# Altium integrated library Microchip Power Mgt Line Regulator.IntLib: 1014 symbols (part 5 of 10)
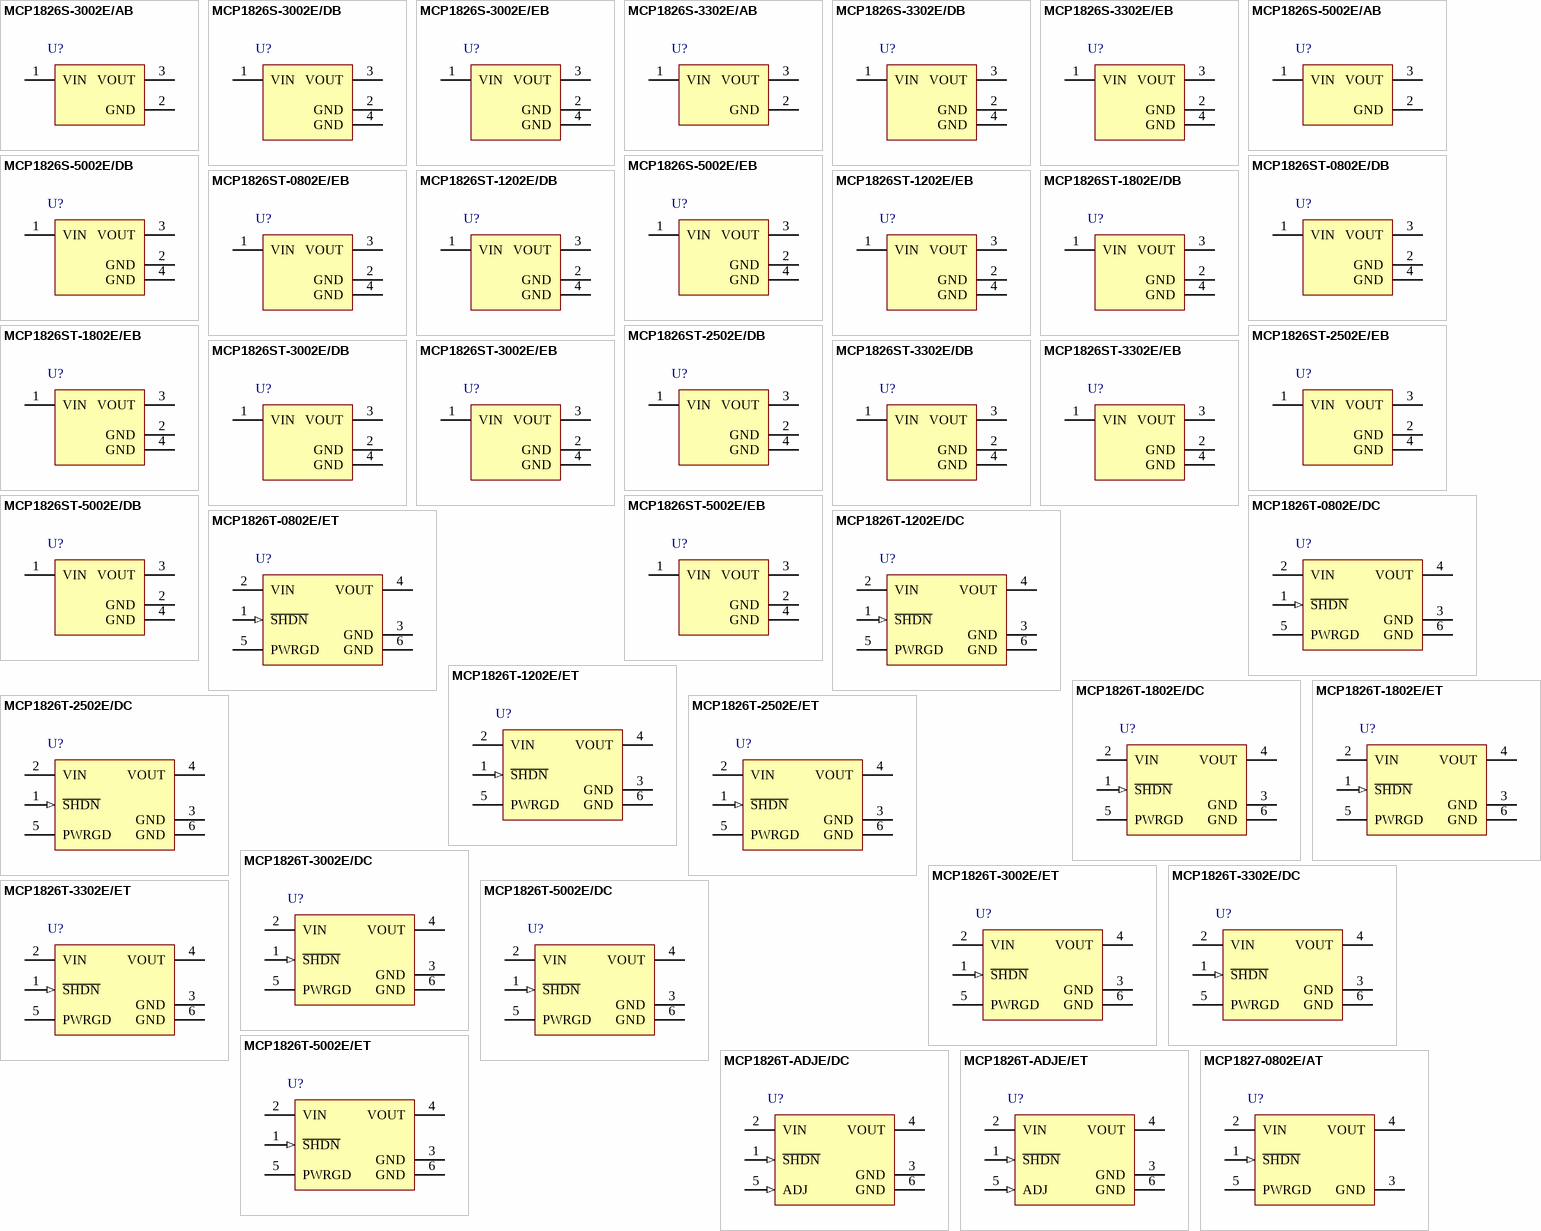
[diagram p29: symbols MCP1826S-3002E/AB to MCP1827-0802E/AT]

## MCP1826T-2502E/DC
designator U?
1000 mA, Low Voltage, Low Quiescent Current LDO Regulator, 5-Pin SOT-223, Extended Temperature, Tape and Reel
footprint SOT-223-DC5_N (SOT223, 6-Leads, Body 6.5x3.5mm, Pitch 1.27mm, Lead Span 7mm, IPC Medium Density)
footprint SOT-223-DC5_L (SOT223, 6-Leads, Body 6.5x3.5mm, Pitch 1.27mm, Lead Span 7mm, IPC High Density)
footprint SOT-223-DC5_M (SOT223, 6-Leads, Body 6.5x3.5mm, Pitch 1.27mm, Lead Span 7mm, IPC Low Density)
pins: 1 ~{SHDN} (in), 2 VIN (power), 3 GND (power), 4 VOUT (power), 5 PWRGD (power), 6 GND (power)

## MCP1826T-2502E/ET
designator U?
1000 mA, Low Voltage, Low Quiescent Current LDO Regulator, 5-Pin DDPAK, Extended Temperature, Tape and Reel
footprint DDPAK-ET5_N (D2-PAK, 6-Leads, Body 9x10.2mm, Pitch 1.7mm, Lead Span 14.9mm, IPC Medium Density)
footprint DDPAK-ET5_L (D2-PAK, 6-Leads, Body 9x10.2mm, Pitch 1.7mm, Lead Span 14.9mm, IPC High Density)
footprint DDPAK-ET5_M (D2-PAK, 6-Leads, Body 9x10.2mm, Pitch 1.7mm, Lead Span 14.9mm, IPC Low Density)
pins: 1 ~{SHDN} (in), 2 VIN (power), 3 GND (power), 4 VOUT (power), 5 PWRGD (power), 6 GND (power)

## MCP1826T-3002E/DC
designator U?
1000 mA, Low Voltage, Low Quiescent Current LDO Regulator, 5-Pin SOT-223, Extended Temperature, Tape and Reel
footprint SOT-223-DC5_N (SOT223, 6-Leads, Body 6.5x3.5mm, Pitch 1.27mm, Lead Span 7mm, IPC Medium Density)
footprint SOT-223-DC5_L (SOT223, 6-Leads, Body 6.5x3.5mm, Pitch 1.27mm, Lead Span 7mm, IPC High Density)
footprint SOT-223-DC5_M (SOT223, 6-Leads, Body 6.5x3.5mm, Pitch 1.27mm, Lead Span 7mm, IPC Low Density)
pins: 1 ~{SHDN} (in), 2 VIN (power), 3 GND (power), 4 VOUT (power), 5 PWRGD (power), 6 GND (power)

## MCP1826T-3002E/ET
designator U?
1000 mA, Low Voltage, Low Quiescent Current LDO Regulator, 5-Pin DDPAK, Extended Temperature, Tape and Reel
footprint DDPAK-ET5_N (D2-PAK, 6-Leads, Body 9x10.2mm, Pitch 1.7mm, Lead Span 14.9mm, IPC Medium Density)
footprint DDPAK-ET5_L (D2-PAK, 6-Leads, Body 9x10.2mm, Pitch 1.7mm, Lead Span 14.9mm, IPC High Density)
footprint DDPAK-ET5_M (D2-PAK, 6-Leads, Body 9x10.2mm, Pitch 1.7mm, Lead Span 14.9mm, IPC Low Density)
pins: 1 ~{SHDN} (in), 2 VIN (power), 3 GND (power), 4 VOUT (power), 5 PWRGD (power), 6 GND (power)

## MCP1826T-3302E/DC
designator U?
1000 mA, Low Voltage, Low Quiescent Current LDO Regulator, 5-Pin SOT-223, Extended Temperature, Tape and Reel
footprint SOT-223-DC5_N (SOT223, 6-Leads, Body 6.5x3.5mm, Pitch 1.27mm, Lead Span 7mm, IPC Medium Density)
footprint SOT-223-DC5_L (SOT223, 6-Leads, Body 6.5x3.5mm, Pitch 1.27mm, Lead Span 7mm, IPC High Density)
footprint SOT-223-DC5_M (SOT223, 6-Leads, Body 6.5x3.5mm, Pitch 1.27mm, Lead Span 7mm, IPC Low Density)
pins: 1 ~{SHDN} (in), 2 VIN (power), 3 GND (power), 4 VOUT (power), 5 PWRGD (power), 6 GND (power)

## MCP1826T-3302E/ET
designator U?
1000 mA, Low Voltage, Low Quiescent Current LDO Regulator, 5-Pin DDPAK, Extended Temperature, Tape and Reel
footprint DDPAK-ET5_N (D2-PAK, 6-Leads, Body 9x10.2mm, Pitch 1.7mm, Lead Span 14.9mm, IPC Medium Density)
footprint DDPAK-ET5_L (D2-PAK, 6-Leads, Body 9x10.2mm, Pitch 1.7mm, Lead Span 14.9mm, IPC High Density)
footprint DDPAK-ET5_M (D2-PAK, 6-Leads, Body 9x10.2mm, Pitch 1.7mm, Lead Span 14.9mm, IPC Low Density)
pins: 1 ~{SHDN} (in), 2 VIN (power), 3 GND (power), 4 VOUT (power), 5 PWRGD (power), 6 GND (power)

## MCP1826T-5002E/DC
designator U?
1000 mA, Low Voltage, Low Quiescent Current LDO Regulator, 5-Pin SOT-223, Extended Temperature, Tape and Reel
footprint SOT-223-DC5_N (SOT223, 6-Leads, Body 6.5x3.5mm, Pitch 1.27mm, Lead Span 7mm, IPC Medium Density)
footprint SOT-223-DC5_L (SOT223, 6-Leads, Body 6.5x3.5mm, Pitch 1.27mm, Lead Span 7mm, IPC High Density)
footprint SOT-223-DC5_M (SOT223, 6-Leads, Body 6.5x3.5mm, Pitch 1.27mm, Lead Span 7mm, IPC Low Density)
pins: 1 ~{SHDN} (in), 2 VIN (power), 3 GND (power), 4 VOUT (power), 5 PWRGD (power), 6 GND (power)

## MCP1826T-5002E/ET
designator U?
1000 mA, Low Voltage, Low Quiescent Current LDO Regulator, 5-Pin DDPAK, Extended Temperature, Tape and Reel
footprint DDPAK-ET5_N (D2-PAK, 6-Leads, Body 9x10.2mm, Pitch 1.7mm, Lead Span 14.9mm, IPC Medium Density)
footprint DDPAK-ET5_L (D2-PAK, 6-Leads, Body 9x10.2mm, Pitch 1.7mm, Lead Span 14.9mm, IPC High Density)
footprint DDPAK-ET5_M (D2-PAK, 6-Leads, Body 9x10.2mm, Pitch 1.7mm, Lead Span 14.9mm, IPC Low Density)
pins: 1 ~{SHDN} (in), 2 VIN (power), 3 GND (power), 4 VOUT (power), 5 PWRGD (power), 6 GND (power)

## MCP1826T-ADJE/DC
designator U?
1000 mA, Low Voltage, Low Quiescent Current LDO Regulator, 5-Pin SOT-223, Extended Temperature, Tape and Reel
footprint SOT-223-DC5_N (SOT223, 6-Leads, Body 6.5x3.5mm, Pitch 1.27mm, Lead Span 7mm, IPC Medium Density)
footprint SOT-223-DC5_L (SOT223, 6-Leads, Body 6.5x3.5mm, Pitch 1.27mm, Lead Span 7mm, IPC High Density)
footprint SOT-223-DC5_M (SOT223, 6-Leads, Body 6.5x3.5mm, Pitch 1.27mm, Lead Span 7mm, IPC Low Density)
pins: 1 ~{SHDN} (in), 2 VIN (power), 3 GND (power), 4 VOUT (power), 5 ADJ (in), 6 GND (power)

## MCP1826T-ADJE/ET
designator U?
1000 mA, Low Voltage, Low Quiescent Current LDO Regulator, 5-Pin DDPAK, Extended Temperature, Tape and Reel
footprint DDPAK-ET5_N (D2-PAK, 6-Leads, Body 9x10.2mm, Pitch 1.7mm, Lead Span 14.9mm, IPC Medium Density)
footprint DDPAK-ET5_L (D2-PAK, 6-Leads, Body 9x10.2mm, Pitch 1.7mm, Lead Span 14.9mm, IPC High Density)
footprint DDPAK-ET5_M (D2-PAK, 6-Leads, Body 9x10.2mm, Pitch 1.7mm, Lead Span 14.9mm, IPC Low Density)
pins: 1 ~{SHDN} (in), 2 VIN (power), 3 GND (power), 4 VOUT (power), 5 ADJ (in), 6 GND (power)

## MCP1827-0802E/AT
designator U?
1.5A, Low Voltage, Low Quiescent Current LDO Regulator, 5-Pin TO-220, Extended Temperature
footprint TO-220-AT5 (TO, Thru-Hole, Vertical, Heatsink Mounted; 5 In-Line Leads; Pitch 1.70 mm)
pins: 1 ~{SHDN} (in), 2 VIN (power), 3 GND (power), 4 VOUT (power), 5 PWRGD (power)

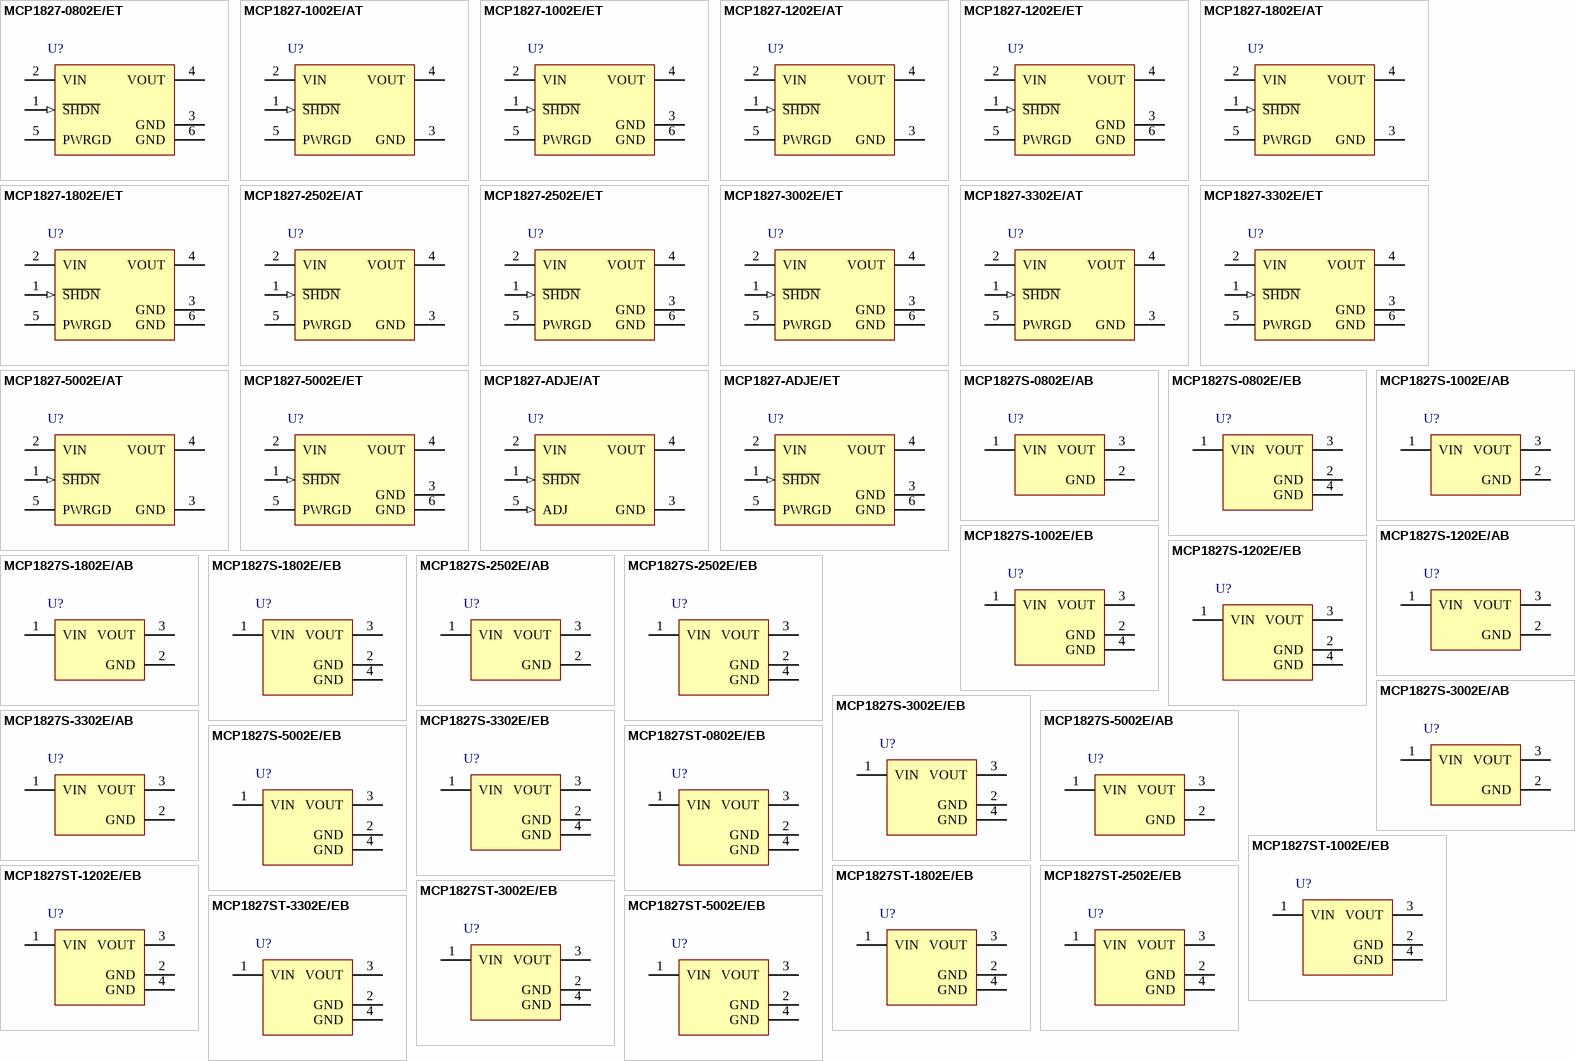
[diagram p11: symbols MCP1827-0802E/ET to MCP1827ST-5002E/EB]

## MCP1827-0802E/ET
designator U?
1.5A, Low Voltage, Low Quiescent Current LDO Regulator, 5-Pin DDPAK, Extended Temperature
footprint DDPAK-ET5_N (D2-PAK, 6-Leads, Body 9x10.2mm, Pitch 1.7mm, Lead Span 14.9mm, IPC Medium Density)
footprint DDPAK-ET5_L (D2-PAK, 6-Leads, Body 9x10.2mm, Pitch 1.7mm, Lead Span 14.9mm, IPC High Density)
footprint DDPAK-ET5_M (D2-PAK, 6-Leads, Body 9x10.2mm, Pitch 1.7mm, Lead Span 14.9mm, IPC Low Density)
pins: 1 ~{SHDN} (in), 2 VIN (power), 3 GND (power), 4 VOUT (power), 5 PWRGD (power), 6 GND (power)

## MCP1827-1002E/AT
designator U?
1.5A, Low Voltage, Low Quiescent Current LDO Regulator, 5-Pin TO-220, Extended Temperature
footprint TO-220-AT5 (TO, Thru-Hole, Vertical, Heatsink Mounted; 5 In-Line Leads; Pitch 1.70 mm)
pins: 1 ~{SHDN} (in), 2 VIN (power), 3 GND (power), 4 VOUT (power), 5 PWRGD (power)

## MCP1827-1002E/ET
designator U?
1.5A, Low Voltage, Low Quiescent Current LDO Regulator, 5-Pin DDPAK, Extended Temperature
footprint DDPAK-ET5_N (D2-PAK, 6-Leads, Body 9x10.2mm, Pitch 1.7mm, Lead Span 14.9mm, IPC Medium Density)
footprint DDPAK-ET5_L (D2-PAK, 6-Leads, Body 9x10.2mm, Pitch 1.7mm, Lead Span 14.9mm, IPC High Density)
footprint DDPAK-ET5_M (D2-PAK, 6-Leads, Body 9x10.2mm, Pitch 1.7mm, Lead Span 14.9mm, IPC Low Density)
pins: 1 ~{SHDN} (in), 2 VIN (power), 3 GND (power), 4 VOUT (power), 5 PWRGD (power), 6 GND (power)

## MCP1827-1202E/AT
designator U?
1.5A, Low Voltage, Low Quiescent Current LDO Regulator, 5-Pin TO-220, Extended Temperature
footprint TO-220-AT5 (TO, Thru-Hole, Vertical, Heatsink Mounted; 5 In-Line Leads; Pitch 1.70 mm)
pins: 1 ~{SHDN} (in), 2 VIN (power), 3 GND (power), 4 VOUT (power), 5 PWRGD (power)

## MCP1827-1202E/ET
designator U?
1.5A, Low Voltage, Low Quiescent Current LDO Regulator, 5-Pin DDPAK, Extended Temperature
footprint DDPAK-ET5_N (D2-PAK, 6-Leads, Body 9x10.2mm, Pitch 1.7mm, Lead Span 14.9mm, IPC Medium Density)
footprint DDPAK-ET5_L (D2-PAK, 6-Leads, Body 9x10.2mm, Pitch 1.7mm, Lead Span 14.9mm, IPC High Density)
footprint DDPAK-ET5_M (D2-PAK, 6-Leads, Body 9x10.2mm, Pitch 1.7mm, Lead Span 14.9mm, IPC Low Density)
pins: 1 ~{SHDN} (in), 2 VIN (power), 3 GND (power), 4 VOUT (power), 5 PWRGD (power), 6 GND (power)

## MCP1827-1802E/AT
designator U?
1.5A, Low Voltage, Low Quiescent Current LDO Regulator, 5-Pin TO-220, Extended Temperature
footprint TO-220-AT5 (TO, Thru-Hole, Vertical, Heatsink Mounted; 5 In-Line Leads; Pitch 1.70 mm)
pins: 1 ~{SHDN} (in), 2 VIN (power), 3 GND (power), 4 VOUT (power), 5 PWRGD (power)

## MCP1827-1802E/ET
designator U?
1.5A, Low Voltage, Low Quiescent Current LDO Regulator, 5-Pin DDPAK, Extended Temperature
footprint DDPAK-ET5_N (D2-PAK, 6-Leads, Body 9x10.2mm, Pitch 1.7mm, Lead Span 14.9mm, IPC Medium Density)
footprint DDPAK-ET5_L (D2-PAK, 6-Leads, Body 9x10.2mm, Pitch 1.7mm, Lead Span 14.9mm, IPC High Density)
footprint DDPAK-ET5_M (D2-PAK, 6-Leads, Body 9x10.2mm, Pitch 1.7mm, Lead Span 14.9mm, IPC Low Density)
pins: 1 ~{SHDN} (in), 2 VIN (power), 3 GND (power), 4 VOUT (power), 5 PWRGD (power), 6 GND (power)

## MCP1827-2502E/AT
designator U?
1.5A, Low Voltage, Low Quiescent Current LDO Regulator, 5-Pin TO-220, Extended Temperature
footprint TO-220-AT5 (TO, Thru-Hole, Vertical, Heatsink Mounted; 5 In-Line Leads; Pitch 1.70 mm)
pins: 1 ~{SHDN} (in), 2 VIN (power), 3 GND (power), 4 VOUT (power), 5 PWRGD (power)

## MCP1827-2502E/ET
designator U?
1.5A, Low Voltage, Low Quiescent Current LDO Regulator, 5-Pin DDPAK, Extended Temperature
footprint DDPAK-ET5_N (D2-PAK, 6-Leads, Body 9x10.2mm, Pitch 1.7mm, Lead Span 14.9mm, IPC Medium Density)
footprint DDPAK-ET5_L (D2-PAK, 6-Leads, Body 9x10.2mm, Pitch 1.7mm, Lead Span 14.9mm, IPC High Density)
footprint DDPAK-ET5_M (D2-PAK, 6-Leads, Body 9x10.2mm, Pitch 1.7mm, Lead Span 14.9mm, IPC Low Density)
pins: 1 ~{SHDN} (in), 2 VIN (power), 3 GND (power), 4 VOUT (power), 5 PWRGD (power), 6 GND (power)

## MCP1827-3002E/ET
designator U?
1.5A, Low Voltage, Low Quiescent Current LDO Regulator, 5-Pin DDPAK, Extended Temperature
footprint DDPAK-ET5_N (D2-PAK, 6-Leads, Body 9x10.2mm, Pitch 1.7mm, Lead Span 14.9mm, IPC Medium Density)
footprint DDPAK-ET5_L (D2-PAK, 6-Leads, Body 9x10.2mm, Pitch 1.7mm, Lead Span 14.9mm, IPC High Density)
footprint DDPAK-ET5_M (D2-PAK, 6-Leads, Body 9x10.2mm, Pitch 1.7mm, Lead Span 14.9mm, IPC Low Density)
pins: 1 ~{SHDN} (in), 2 VIN (power), 3 GND (power), 4 VOUT (power), 5 PWRGD (power), 6 GND (power)

## MCP1827-3302E/AT
designator U?
1.5A, Low Voltage, Low Quiescent Current LDO Regulator, 5-Pin TO-220, Extended Temperature
footprint TO-220-AT5 (TO, Thru-Hole, Vertical, Heatsink Mounted; 5 In-Line Leads; Pitch 1.70 mm)
pins: 1 ~{SHDN} (in), 2 VIN (power), 3 GND (power), 4 VOUT (power), 5 PWRGD (power)

## MCP1827-3302E/ET
designator U?
1.5A, Low Voltage, Low Quiescent Current LDO Regulator, 5-Pin DDPAK, Extended Temperature
footprint DDPAK-ET5_N (D2-PAK, 6-Leads, Body 9x10.2mm, Pitch 1.7mm, Lead Span 14.9mm, IPC Medium Density)
footprint DDPAK-ET5_L (D2-PAK, 6-Leads, Body 9x10.2mm, Pitch 1.7mm, Lead Span 14.9mm, IPC High Density)
footprint DDPAK-ET5_M (D2-PAK, 6-Leads, Body 9x10.2mm, Pitch 1.7mm, Lead Span 14.9mm, IPC Low Density)
pins: 1 ~{SHDN} (in), 2 VIN (power), 3 GND (power), 4 VOUT (power), 5 PWRGD (power), 6 GND (power)

## MCP1827-5002E/AT
designator U?
1.5A, Low Voltage, Low Quiescent Current LDO Regulator, 5-Pin TO-220, Extended Temperature
footprint TO-220-AT5 (TO, Thru-Hole, Vertical, Heatsink Mounted; 5 In-Line Leads; Pitch 1.70 mm)
pins: 1 ~{SHDN} (in), 2 VIN (power), 3 GND (power), 4 VOUT (power), 5 PWRGD (power)

## MCP1827-5002E/ET
designator U?
1.5A, Low Voltage, Low Quiescent Current LDO Regulator, 5-Pin DDPAK, Extended Temperature
footprint DDPAK-ET5_N (D2-PAK, 6-Leads, Body 9x10.2mm, Pitch 1.7mm, Lead Span 14.9mm, IPC Medium Density)
footprint DDPAK-ET5_L (D2-PAK, 6-Leads, Body 9x10.2mm, Pitch 1.7mm, Lead Span 14.9mm, IPC High Density)
footprint DDPAK-ET5_M (D2-PAK, 6-Leads, Body 9x10.2mm, Pitch 1.7mm, Lead Span 14.9mm, IPC Low Density)
pins: 1 ~{SHDN} (in), 2 VIN (power), 3 GND (power), 4 VOUT (power), 5 PWRGD (power), 6 GND (power)

## MCP1827-ADJE/AT
designator U?
1.5A, Low Voltage, Low Quiescent Current LDO Regulator, 5-Pin TO-220, Extended Temperature
footprint TO-220-AT5 (TO, Thru-Hole, Vertical, Heatsink Mounted; 5 In-Line Leads; Pitch 1.70 mm)
pins: 1 ~{SHDN} (in), 2 VIN (power), 3 GND (power), 4 VOUT (power), 5 ADJ (in)

## MCP1827-ADJE/ET
designator U?
1.5A, Low Voltage, Low Quiescent Current LDO Regulator, 5-Pin DDPAK, Extended Temperature
footprint DDPAK-ET5_N (D2-PAK, 6-Leads, Body 9x10.2mm, Pitch 1.7mm, Lead Span 14.9mm, IPC Medium Density)
footprint DDPAK-ET5_L (D2-PAK, 6-Leads, Body 9x10.2mm, Pitch 1.7mm, Lead Span 14.9mm, IPC High Density)
footprint DDPAK-ET5_M (D2-PAK, 6-Leads, Body 9x10.2mm, Pitch 1.7mm, Lead Span 14.9mm, IPC Low Density)
pins: 1 ~{SHDN} (in), 2 VIN (power), 3 GND (power), 4 VOUT (power), 5 PWRGD (power), 6 GND (power)

## MCP1827S-0802E/AB
designator U?
1.5A, Low Voltage, Low Quiescent Current LDO Regulator, 3-Pin TO-220, Extended Temperature
footprint TO-220-AB3 (TO, Thru-Hole, Vertical, Heatsink Mounted; 3 In-Line Leads; Pitch 2.54 mm)
pins: 1 VIN (power), 2 GND (power), 3 VOUT (power)

## MCP1827S-0802E/EB
designator U?
1.5A, Low Voltage, Low Quiescent Current LDO Regulator, 3-Pin DDPAK, Extended Temperature
footprint DDPAK-EB3_N (D2-PAK, 4-Leads, Body 9x10.2mm, Pitch 2.54mm, Lead Span 14.9mm, IPC Medium Density)
footprint DDPAK-EB3_L (D2-PAK, 4-Leads, Body 9x10.2mm, Pitch 2.54mm, Lead Span 14.9mm, IPC High Density)
footprint DDPAK-EB3_M (D2-PAK, 4-Leads, Body 9x10.2mm, Pitch 2.54mm, Lead Span 14.9mm, IPC Low Density)
pins: 1 VIN (power), 2 GND (power), 3 VOUT (power), 4 GND (power)

## MCP1827S-1002E/AB
designator U?
1.5A, Low Voltage, Low Quiescent Current LDO Regulator, 3-Pin TO-220, Extended Temperature
footprint TO-220-AB3 (TO, Thru-Hole, Vertical, Heatsink Mounted; 3 In-Line Leads; Pitch 2.54 mm)
pins: 1 VIN (power), 2 GND (power), 3 VOUT (power)

## MCP1827S-1002E/EB
designator U?
1.5A, Low Voltage, Low Quiescent Current LDO Regulator, 3-Pin DDPAK, Extended Temperature
footprint DDPAK-EB3_N (D2-PAK, 4-Leads, Body 9x10.2mm, Pitch 2.54mm, Lead Span 14.9mm, IPC Medium Density)
footprint DDPAK-EB3_L (D2-PAK, 4-Leads, Body 9x10.2mm, Pitch 2.54mm, Lead Span 14.9mm, IPC High Density)
footprint DDPAK-EB3_M (D2-PAK, 4-Leads, Body 9x10.2mm, Pitch 2.54mm, Lead Span 14.9mm, IPC Low Density)
pins: 1 VIN (power), 2 GND (power), 3 VOUT (power), 4 GND (power)

## MCP1827S-1202E/AB
designator U?
1.5A, Low Voltage, Low Quiescent Current LDO Regulator, 3-Pin TO-220, Extended Temperature
footprint TO-220-AB3 (TO, Thru-Hole, Vertical, Heatsink Mounted; 3 In-Line Leads; Pitch 2.54 mm)
pins: 1 VIN (power), 2 GND (power), 3 VOUT (power)

## MCP1827S-1202E/EB
designator U?
1.5A, Low Voltage, Low Quiescent Current LDO Regulator, 3-Pin DDPAK, Extended Temperature
footprint DDPAK-EB3_N (D2-PAK, 4-Leads, Body 9x10.2mm, Pitch 2.54mm, Lead Span 14.9mm, IPC Medium Density)
footprint DDPAK-EB3_L (D2-PAK, 4-Leads, Body 9x10.2mm, Pitch 2.54mm, Lead Span 14.9mm, IPC High Density)
footprint DDPAK-EB3_M (D2-PAK, 4-Leads, Body 9x10.2mm, Pitch 2.54mm, Lead Span 14.9mm, IPC Low Density)
pins: 1 VIN (power), 2 GND (power), 3 VOUT (power), 4 GND (power)

## MCP1827S-1802E/AB
designator U?
1.5A, Low Voltage, Low Quiescent Current LDO Regulator, 3-Pin TO-220, Extended Temperature
footprint TO-220-AB3 (TO, Thru-Hole, Vertical, Heatsink Mounted; 3 In-Line Leads; Pitch 2.54 mm)
pins: 1 VIN (power), 2 GND (power), 3 VOUT (power)

## MCP1827S-1802E/EB
designator U?
1.5A, Low Voltage, Low Quiescent Current LDO Regulator, 3-Pin DDPAK, Extended Temperature
footprint DDPAK-EB3_N (D2-PAK, 4-Leads, Body 9x10.2mm, Pitch 2.54mm, Lead Span 14.9mm, IPC Medium Density)
footprint DDPAK-EB3_L (D2-PAK, 4-Leads, Body 9x10.2mm, Pitch 2.54mm, Lead Span 14.9mm, IPC High Density)
footprint DDPAK-EB3_M (D2-PAK, 4-Leads, Body 9x10.2mm, Pitch 2.54mm, Lead Span 14.9mm, IPC Low Density)
pins: 1 VIN (power), 2 GND (power), 3 VOUT (power), 4 GND (power)

## MCP1827S-2502E/AB
designator U?
1.5A, Low Voltage, Low Quiescent Current LDO Regulator, 3-Pin TO-220, Extended Temperature
footprint TO-220-AB3 (TO, Thru-Hole, Vertical, Heatsink Mounted; 3 In-Line Leads; Pitch 2.54 mm)
pins: 1 VIN (power), 2 GND (power), 3 VOUT (power)

## MCP1827S-2502E/EB
designator U?
1.5A, Low Voltage, Low Quiescent Current LDO Regulator, 3-Pin DDPAK, Extended Temperature
footprint DDPAK-EB3_N (D2-PAK, 4-Leads, Body 9x10.2mm, Pitch 2.54mm, Lead Span 14.9mm, IPC Medium Density)
footprint DDPAK-EB3_L (D2-PAK, 4-Leads, Body 9x10.2mm, Pitch 2.54mm, Lead Span 14.9mm, IPC High Density)
footprint DDPAK-EB3_M (D2-PAK, 4-Leads, Body 9x10.2mm, Pitch 2.54mm, Lead Span 14.9mm, IPC Low Density)
pins: 1 VIN (power), 2 GND (power), 3 VOUT (power), 4 GND (power)

## MCP1827S-3002E/AB
designator U?
1.5A, Low Voltage, Low Quiescent Current LDO Regulator, 3-Pin TO-220, Extended Temperature
footprint TO-220-AB3 (TO, Thru-Hole, Vertical, Heatsink Mounted; 3 In-Line Leads; Pitch 2.54 mm)
pins: 1 VIN (power), 2 GND (power), 3 VOUT (power)

## MCP1827S-3002E/EB
designator U?
1.5A, Low Voltage, Low Quiescent Current LDO Regulator, 3-Pin DDPAK, Extended Temperature
footprint DDPAK-EB3_N (D2-PAK, 4-Leads, Body 9x10.2mm, Pitch 2.54mm, Lead Span 14.9mm, IPC Medium Density)
footprint DDPAK-EB3_L (D2-PAK, 4-Leads, Body 9x10.2mm, Pitch 2.54mm, Lead Span 14.9mm, IPC High Density)
footprint DDPAK-EB3_M (D2-PAK, 4-Leads, Body 9x10.2mm, Pitch 2.54mm, Lead Span 14.9mm, IPC Low Density)
pins: 1 VIN (power), 2 GND (power), 3 VOUT (power), 4 GND (power)

## MCP1827S-3302E/AB
designator U?
1.5A, Low Voltage, Low Quiescent Current LDO Regulator, 3-Pin TO-220, Extended Temperature
footprint TO-220-AB3 (TO, Thru-Hole, Vertical, Heatsink Mounted; 3 In-Line Leads; Pitch 2.54 mm)
pins: 1 VIN (power), 2 GND (power), 3 VOUT (power)

## MCP1827S-3302E/EB
designator U?
1.5A, Low Voltage, Low Quiescent Current LDO Regulator, 3-Pin DDPAK, Extended Temperature
footprint DDPAK-EB3_N (D2-PAK, 4-Leads, Body 9x10.2mm, Pitch 2.54mm, Lead Span 14.9mm, IPC Medium Density)
footprint DDPAK-EB3_L (D2-PAK, 4-Leads, Body 9x10.2mm, Pitch 2.54mm, Lead Span 14.9mm, IPC High Density)
footprint DDPAK-EB3_M (D2-PAK, 4-Leads, Body 9x10.2mm, Pitch 2.54mm, Lead Span 14.9mm, IPC Low Density)
pins: 1 VIN (power), 2 GND (power), 3 VOUT (power), 4 GND (power)

## MCP1827S-5002E/AB
designator U?
1.5A, Low Voltage, Low Quiescent Current LDO Regulator, 3-Pin TO-220, Extended Temperature
footprint TO-220-AB3 (TO, Thru-Hole, Vertical, Heatsink Mounted; 3 In-Line Leads; Pitch 2.54 mm)
pins: 1 VIN (power), 2 GND (power), 3 VOUT (power)

## MCP1827S-5002E/EB
designator U?
1.5A, Low Voltage, Low Quiescent Current LDO Regulator, 3-Pin DDPAK, Extended Temperature
footprint DDPAK-EB3_N (D2-PAK, 4-Leads, Body 9x10.2mm, Pitch 2.54mm, Lead Span 14.9mm, IPC Medium Density)
footprint DDPAK-EB3_L (D2-PAK, 4-Leads, Body 9x10.2mm, Pitch 2.54mm, Lead Span 14.9mm, IPC High Density)
footprint DDPAK-EB3_M (D2-PAK, 4-Leads, Body 9x10.2mm, Pitch 2.54mm, Lead Span 14.9mm, IPC Low Density)
pins: 1 VIN (power), 2 GND (power), 3 VOUT (power), 4 GND (power)

## MCP1827ST-0802E/EB
designator U?
1.5A, Low Voltage, Low Quiescent Current LDO Regulator, 3-Pin DDPAK, Extended Temperature, Tape and Reel
footprint DDPAK-EB3_N (D2-PAK, 4-Leads, Body 9x10.2mm, Pitch 2.54mm, Lead Span 14.9mm, IPC Medium Density)
footprint DDPAK-EB3_L (D2-PAK, 4-Leads, Body 9x10.2mm, Pitch 2.54mm, Lead Span 14.9mm, IPC High Density)
footprint DDPAK-EB3_M (D2-PAK, 4-Leads, Body 9x10.2mm, Pitch 2.54mm, Lead Span 14.9mm, IPC Low Density)
pins: 1 VIN (power), 2 GND (power), 3 VOUT (power), 4 GND (power)

## MCP1827ST-1002E/EB
designator U?
1.5A, Low Voltage, Low Quiescent Current LDO Regulator, 3-Pin DDPAK, Extended Temperature, Tape and Reel
footprint DDPAK-EB3_N (D2-PAK, 4-Leads, Body 9x10.2mm, Pitch 2.54mm, Lead Span 14.9mm, IPC Medium Density)
footprint DDPAK-EB3_L (D2-PAK, 4-Leads, Body 9x10.2mm, Pitch 2.54mm, Lead Span 14.9mm, IPC High Density)
footprint DDPAK-EB3_M (D2-PAK, 4-Leads, Body 9x10.2mm, Pitch 2.54mm, Lead Span 14.9mm, IPC Low Density)
pins: 1 VIN (power), 2 GND (power), 3 VOUT (power), 4 GND (power)

## MCP1827ST-1202E/EB
designator U?
1.5A, Low Voltage, Low Quiescent Current LDO Regulator, 3-Pin DDPAK, Extended Temperature, Tape and Reel
footprint DDPAK-EB3_N (D2-PAK, 4-Leads, Body 9x10.2mm, Pitch 2.54mm, Lead Span 14.9mm, IPC Medium Density)
footprint DDPAK-EB3_L (D2-PAK, 4-Leads, Body 9x10.2mm, Pitch 2.54mm, Lead Span 14.9mm, IPC High Density)
footprint DDPAK-EB3_M (D2-PAK, 4-Leads, Body 9x10.2mm, Pitch 2.54mm, Lead Span 14.9mm, IPC Low Density)
pins: 1 VIN (power), 2 GND (power), 3 VOUT (power), 4 GND (power)

## MCP1827ST-1802E/EB
designator U?
1.5A, Low Voltage, Low Quiescent Current LDO Regulator, 3-Pin DDPAK, Extended Temperature, Tape and Reel
footprint DDPAK-EB3_N (D2-PAK, 4-Leads, Body 9x10.2mm, Pitch 2.54mm, Lead Span 14.9mm, IPC Medium Density)
footprint DDPAK-EB3_L (D2-PAK, 4-Leads, Body 9x10.2mm, Pitch 2.54mm, Lead Span 14.9mm, IPC High Density)
footprint DDPAK-EB3_M (D2-PAK, 4-Leads, Body 9x10.2mm, Pitch 2.54mm, Lead Span 14.9mm, IPC Low Density)
pins: 1 VIN (power), 2 GND (power), 3 VOUT (power), 4 GND (power)

## MCP1827ST-2502E/EB
designator U?
1.5A, Low Voltage, Low Quiescent Current LDO Regulator, 3-Pin DDPAK, Extended Temperature, Tape and Reel
footprint DDPAK-EB3_N (D2-PAK, 4-Leads, Body 9x10.2mm, Pitch 2.54mm, Lead Span 14.9mm, IPC Medium Density)
footprint DDPAK-EB3_L (D2-PAK, 4-Leads, Body 9x10.2mm, Pitch 2.54mm, Lead Span 14.9mm, IPC High Density)
footprint DDPAK-EB3_M (D2-PAK, 4-Leads, Body 9x10.2mm, Pitch 2.54mm, Lead Span 14.9mm, IPC Low Density)
pins: 1 VIN (power), 2 GND (power), 3 VOUT (power), 4 GND (power)

## MCP1827ST-3002E/EB
designator U?
1.5A, Low Voltage, Low Quiescent Current LDO Regulator, 3-Pin DDPAK, Extended Temperature, Tape and Reel
footprint DDPAK-EB3_N (D2-PAK, 4-Leads, Body 9x10.2mm, Pitch 2.54mm, Lead Span 14.9mm, IPC Medium Density)
footprint DDPAK-EB3_L (D2-PAK, 4-Leads, Body 9x10.2mm, Pitch 2.54mm, Lead Span 14.9mm, IPC High Density)
footprint DDPAK-EB3_M (D2-PAK, 4-Leads, Body 9x10.2mm, Pitch 2.54mm, Lead Span 14.9mm, IPC Low Density)
pins: 1 VIN (power), 2 GND (power), 3 VOUT (power), 4 GND (power)

## MCP1827ST-3302E/EB
designator U?
1.5A, Low Voltage, Low Quiescent Current LDO Regulator, 3-Pin DDPAK, Extended Temperature, Tape and Reel
footprint DDPAK-EB3_N (D2-PAK, 4-Leads, Body 9x10.2mm, Pitch 2.54mm, Lead Span 14.9mm, IPC Medium Density)
footprint DDPAK-EB3_L (D2-PAK, 4-Leads, Body 9x10.2mm, Pitch 2.54mm, Lead Span 14.9mm, IPC High Density)
footprint DDPAK-EB3_M (D2-PAK, 4-Leads, Body 9x10.2mm, Pitch 2.54mm, Lead Span 14.9mm, IPC Low Density)
pins: 1 VIN (power), 2 GND (power), 3 VOUT (power), 4 GND (power)

## MCP1827ST-5002E/EB
designator U?
1.5A, Low Voltage, Low Quiescent Current LDO Regulator, 3-Pin DDPAK, Extended Temperature, Tape and Reel
footprint DDPAK-EB3_N (D2-PAK, 4-Leads, Body 9x10.2mm, Pitch 2.54mm, Lead Span 14.9mm, IPC Medium Density)
footprint DDPAK-EB3_L (D2-PAK, 4-Leads, Body 9x10.2mm, Pitch 2.54mm, Lead Span 14.9mm, IPC High Density)
footprint DDPAK-EB3_M (D2-PAK, 4-Leads, Body 9x10.2mm, Pitch 2.54mm, Lead Span 14.9mm, IPC Low Density)
pins: 1 VIN (power), 2 GND (power), 3 VOUT (power), 4 GND (power)

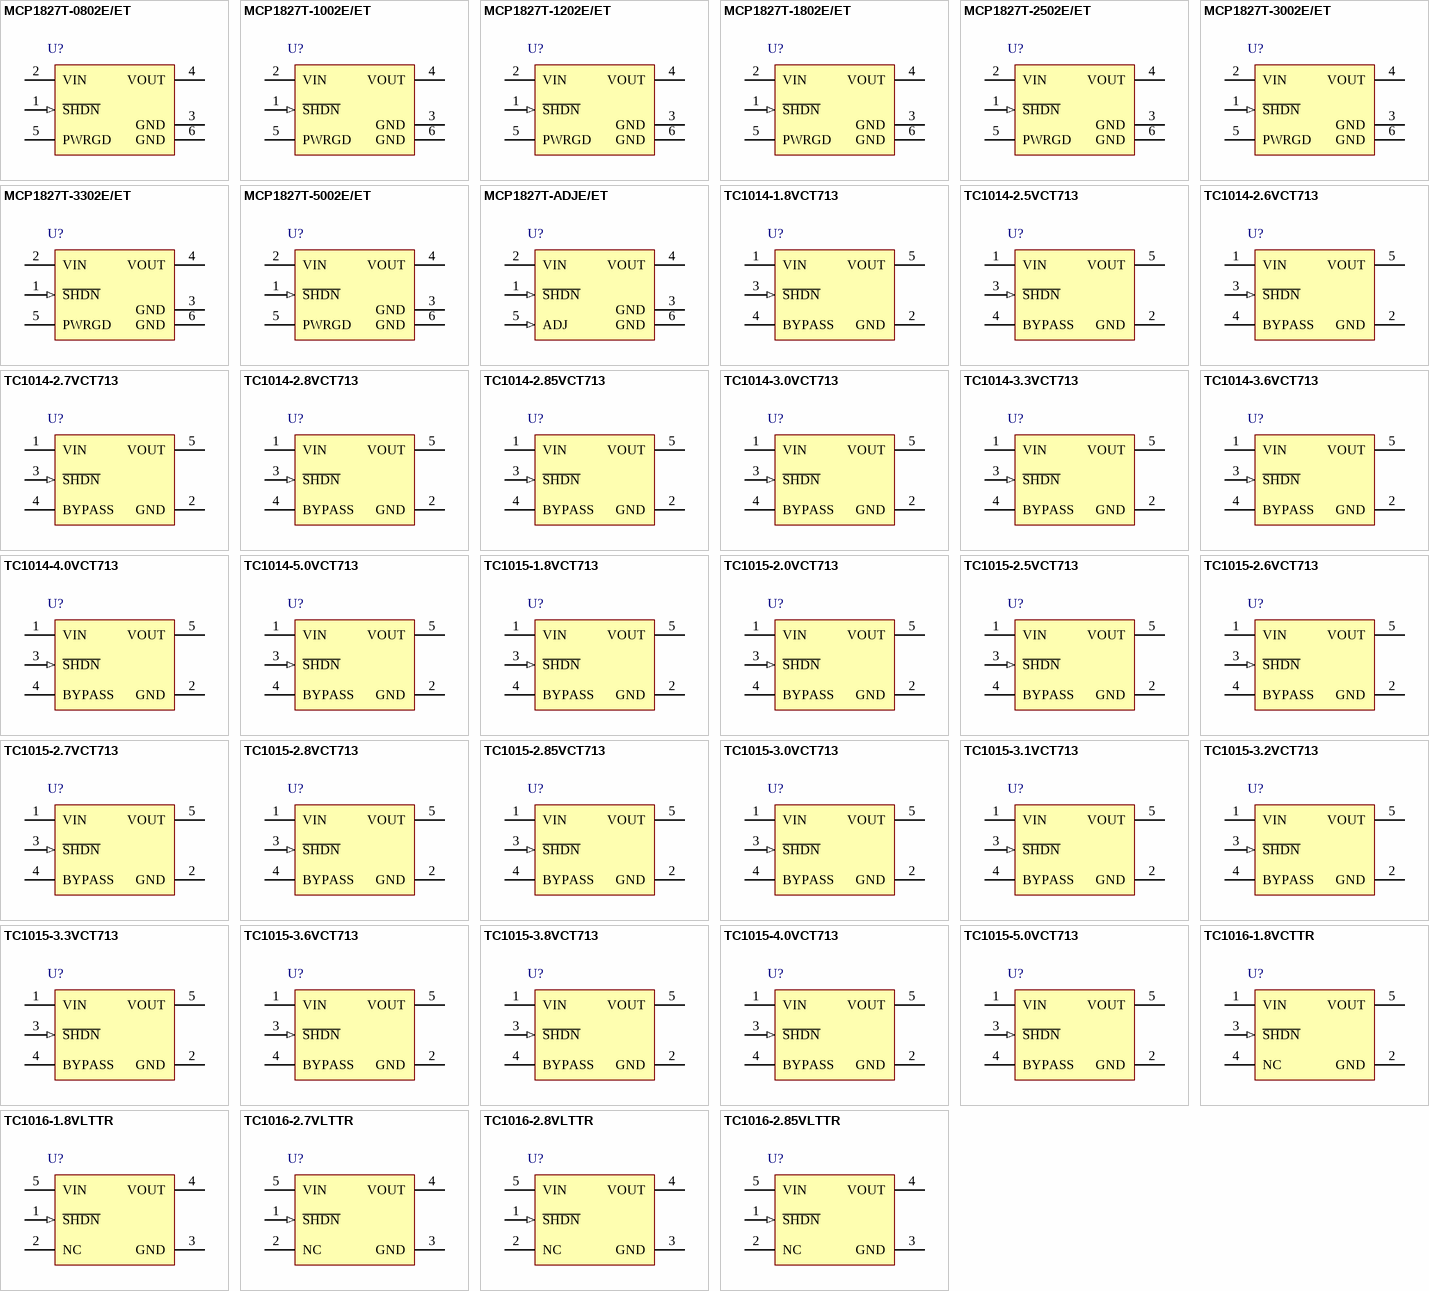
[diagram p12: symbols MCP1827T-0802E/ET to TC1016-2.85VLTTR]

## MCP1827T-0802E/ET
designator U?
1.5A, Low Voltage, Low Quiescent Current LDO Regulator, 5-Pin DDPAK, Extended Temperature, Tape and Reel
footprint DDPAK-ET5_N (D2-PAK, 6-Leads, Body 9x10.2mm, Pitch 1.7mm, Lead Span 14.9mm, IPC Medium Density)
footprint DDPAK-ET5_L (D2-PAK, 6-Leads, Body 9x10.2mm, Pitch 1.7mm, Lead Span 14.9mm, IPC High Density)
footprint DDPAK-ET5_M (D2-PAK, 6-Leads, Body 9x10.2mm, Pitch 1.7mm, Lead Span 14.9mm, IPC Low Density)
pins: 1 ~{SHDN} (in), 2 VIN (power), 3 GND (power), 4 VOUT (power), 5 PWRGD (power), 6 GND (power)

## MCP1827T-1002E/ET
designator U?
1.5A, Low Voltage, Low Quiescent Current LDO Regulator, 5-Pin DDPAK, Extended Temperature, Tape and Reel
footprint DDPAK-ET5_N (D2-PAK, 6-Leads, Body 9x10.2mm, Pitch 1.7mm, Lead Span 14.9mm, IPC Medium Density)
footprint DDPAK-ET5_L (D2-PAK, 6-Leads, Body 9x10.2mm, Pitch 1.7mm, Lead Span 14.9mm, IPC High Density)
footprint DDPAK-ET5_M (D2-PAK, 6-Leads, Body 9x10.2mm, Pitch 1.7mm, Lead Span 14.9mm, IPC Low Density)
pins: 1 ~{SHDN} (in), 2 VIN (power), 3 GND (power), 4 VOUT (power), 5 PWRGD (power), 6 GND (power)

## MCP1827T-1202E/ET
designator U?
1.5A, Low Voltage, Low Quiescent Current LDO Regulator, 5-Pin DDPAK, Extended Temperature, Tape and Reel
footprint DDPAK-ET5_N (D2-PAK, 6-Leads, Body 9x10.2mm, Pitch 1.7mm, Lead Span 14.9mm, IPC Medium Density)
footprint DDPAK-ET5_L (D2-PAK, 6-Leads, Body 9x10.2mm, Pitch 1.7mm, Lead Span 14.9mm, IPC High Density)
footprint DDPAK-ET5_M (D2-PAK, 6-Leads, Body 9x10.2mm, Pitch 1.7mm, Lead Span 14.9mm, IPC Low Density)
pins: 1 ~{SHDN} (in), 2 VIN (power), 3 GND (power), 4 VOUT (power), 5 PWRGD (power), 6 GND (power)

## MCP1827T-1802E/ET
designator U?
1.5A, Low Voltage, Low Quiescent Current LDO Regulator, 5-Pin DDPAK, Extended Temperature, Tape and Reel
footprint DDPAK-ET5_N (D2-PAK, 6-Leads, Body 9x10.2mm, Pitch 1.7mm, Lead Span 14.9mm, IPC Medium Density)
footprint DDPAK-ET5_L (D2-PAK, 6-Leads, Body 9x10.2mm, Pitch 1.7mm, Lead Span 14.9mm, IPC High Density)
footprint DDPAK-ET5_M (D2-PAK, 6-Leads, Body 9x10.2mm, Pitch 1.7mm, Lead Span 14.9mm, IPC Low Density)
pins: 1 ~{SHDN} (in), 2 VIN (power), 3 GND (power), 4 VOUT (power), 5 PWRGD (power), 6 GND (power)

## MCP1827T-2502E/ET
designator U?
1.5A, Low Voltage, Low Quiescent Current LDO Regulator, 5-Pin DDPAK, Extended Temperature, Tape and Reel
footprint DDPAK-ET5_N (D2-PAK, 6-Leads, Body 9x10.2mm, Pitch 1.7mm, Lead Span 14.9mm, IPC Medium Density)
footprint DDPAK-ET5_L (D2-PAK, 6-Leads, Body 9x10.2mm, Pitch 1.7mm, Lead Span 14.9mm, IPC High Density)
footprint DDPAK-ET5_M (D2-PAK, 6-Leads, Body 9x10.2mm, Pitch 1.7mm, Lead Span 14.9mm, IPC Low Density)
pins: 1 ~{SHDN} (in), 2 VIN (power), 3 GND (power), 4 VOUT (power), 5 PWRGD (power), 6 GND (power)

## MCP1827T-3002E/ET
designator U?
1.5A, Low Voltage, Low Quiescent Current LDO Regulator, 5-Pin DDPAK, Extended Temperature, Tape and Reel
footprint DDPAK-ET5_N (D2-PAK, 6-Leads, Body 9x10.2mm, Pitch 1.7mm, Lead Span 14.9mm, IPC Medium Density)
footprint DDPAK-ET5_L (D2-PAK, 6-Leads, Body 9x10.2mm, Pitch 1.7mm, Lead Span 14.9mm, IPC High Density)
footprint DDPAK-ET5_M (D2-PAK, 6-Leads, Body 9x10.2mm, Pitch 1.7mm, Lead Span 14.9mm, IPC Low Density)
pins: 1 ~{SHDN} (in), 2 VIN (power), 3 GND (power), 4 VOUT (power), 5 PWRGD (power), 6 GND (power)

## MCP1827T-3302E/ET
designator U?
1.5A, Low Voltage, Low Quiescent Current LDO Regulator, 5-Pin DDPAK, Extended Temperature, Tape and Reel
footprint DDPAK-ET5_N (D2-PAK, 6-Leads, Body 9x10.2mm, Pitch 1.7mm, Lead Span 14.9mm, IPC Medium Density)
footprint DDPAK-ET5_L (D2-PAK, 6-Leads, Body 9x10.2mm, Pitch 1.7mm, Lead Span 14.9mm, IPC High Density)
footprint DDPAK-ET5_M (D2-PAK, 6-Leads, Body 9x10.2mm, Pitch 1.7mm, Lead Span 14.9mm, IPC Low Density)
pins: 1 ~{SHDN} (in), 2 VIN (power), 3 GND (power), 4 VOUT (power), 5 PWRGD (power), 6 GND (power)

## MCP1827T-5002E/ET
designator U?
1.5A, Low Voltage, Low Quiescent Current LDO Regulator, 5-Pin DDPAK, Extended Temperature, Tape and Reel
footprint DDPAK-ET5_N (D2-PAK, 6-Leads, Body 9x10.2mm, Pitch 1.7mm, Lead Span 14.9mm, IPC Medium Density)
footprint DDPAK-ET5_L (D2-PAK, 6-Leads, Body 9x10.2mm, Pitch 1.7mm, Lead Span 14.9mm, IPC High Density)
footprint DDPAK-ET5_M (D2-PAK, 6-Leads, Body 9x10.2mm, Pitch 1.7mm, Lead Span 14.9mm, IPC Low Density)
pins: 1 ~{SHDN} (in), 2 VIN (power), 3 GND (power), 4 VOUT (power), 5 PWRGD (power), 6 GND (power)

## MCP1827T-ADJE/ET
designator U?
1.5A, Low Voltage, Low Quiescent Current LDO Regulator, 5-Pin DDPAK, Extended Temperature, Tape and Reel
footprint DDPAK-ET5_N (D2-PAK, 6-Leads, Body 9x10.2mm, Pitch 1.7mm, Lead Span 14.9mm, IPC Medium Density)
footprint DDPAK-ET5_L (D2-PAK, 6-Leads, Body 9x10.2mm, Pitch 1.7mm, Lead Span 14.9mm, IPC High Density)
footprint DDPAK-ET5_M (D2-PAK, 6-Leads, Body 9x10.2mm, Pitch 1.7mm, Lead Span 14.9mm, IPC Low Density)
pins: 1 ~{SHDN} (in), 2 VIN (power), 3 GND (power), 4 VOUT (power), 5 ADJ (in), 6 GND (power)

## TC1014-1.8VCT713
designator U?
50 mA, 100 mA and 150 mA CMOS LDOs with Active-Low Shutdown and Reference Bypass, 5-Pin SOT-23, Extended Temperature, Tape and Reel
footprint SOT-23-CT5_N (SOT23, 5-Leads, Body 2.9x1.6mm, Pitch 0.95mm, Lead Span 2.7mm, IPC Medium Density)
footprint SOT-23-CT5_L (SOT23, 5-Leads, Body 2.9x1.6mm, Pitch 0.95mm, Lead Span 2.7mm, IPC High Density)
footprint SOT-23-CT5_M (SOT23, 5-Leads, Body 2.9x1.6mm, Pitch 0.95mm, Lead Span 2.7mm, IPC Low Density)
pins: 1 VIN (power), 2 GND (power), 3 ~{SHDN} (in), 4 BYPASS, 5 VOUT (power)

## TC1014-2.5VCT713
designator U?
50 mA, 100 mA and 150 mA CMOS LDOs with Active-Low Shutdown and Reference Bypass, 5-Pin SOT-23, Extended Temperature, Tape and Reel
footprint SOT-23-CT5_N (SOT23, 5-Leads, Body 2.9x1.6mm, Pitch 0.95mm, Lead Span 2.7mm, IPC Medium Density)
footprint SOT-23-CT5_L (SOT23, 5-Leads, Body 2.9x1.6mm, Pitch 0.95mm, Lead Span 2.7mm, IPC High Density)
footprint SOT-23-CT5_M (SOT23, 5-Leads, Body 2.9x1.6mm, Pitch 0.95mm, Lead Span 2.7mm, IPC Low Density)
pins: 1 VIN (power), 2 GND (power), 3 ~{SHDN} (in), 4 BYPASS, 5 VOUT (power)

## TC1014-2.6VCT713
designator U?
50 mA, 100 mA and 150 mA CMOS LDOs with Active-Low Shutdown and Reference Bypass, 5-Pin SOT-23, Extended Temperature, Tape and Reel
footprint SOT-23-CT5_N (SOT23, 5-Leads, Body 2.9x1.6mm, Pitch 0.95mm, Lead Span 2.7mm, IPC Medium Density)
footprint SOT-23-CT5_L (SOT23, 5-Leads, Body 2.9x1.6mm, Pitch 0.95mm, Lead Span 2.7mm, IPC High Density)
footprint SOT-23-CT5_M (SOT23, 5-Leads, Body 2.9x1.6mm, Pitch 0.95mm, Lead Span 2.7mm, IPC Low Density)
pins: 1 VIN (power), 2 GND (power), 3 ~{SHDN} (in), 4 BYPASS, 5 VOUT (power)

## TC1014-2.7VCT713
designator U?
50 mA, 100 mA and 150 mA CMOS LDOs with Active-Low Shutdown and Reference Bypass, 5-Pin SOT-23, Extended Temperature, Tape and Reel
footprint SOT-23-CT5_N (SOT23, 5-Leads, Body 2.9x1.6mm, Pitch 0.95mm, Lead Span 2.7mm, IPC Medium Density)
footprint SOT-23-CT5_L (SOT23, 5-Leads, Body 2.9x1.6mm, Pitch 0.95mm, Lead Span 2.7mm, IPC High Density)
footprint SOT-23-CT5_M (SOT23, 5-Leads, Body 2.9x1.6mm, Pitch 0.95mm, Lead Span 2.7mm, IPC Low Density)
pins: 1 VIN (power), 2 GND (power), 3 ~{SHDN} (in), 4 BYPASS, 5 VOUT (power)

## TC1014-2.8VCT713
designator U?
50 mA, 100 mA and 150 mA CMOS LDOs with Active-Low Shutdown and Reference Bypass, 5-Pin SOT-23, Extended Temperature, Tape and Reel
footprint SOT-23-CT5_N (SOT23, 5-Leads, Body 2.9x1.6mm, Pitch 0.95mm, Lead Span 2.7mm, IPC Medium Density)
footprint SOT-23-CT5_L (SOT23, 5-Leads, Body 2.9x1.6mm, Pitch 0.95mm, Lead Span 2.7mm, IPC High Density)
footprint SOT-23-CT5_M (SOT23, 5-Leads, Body 2.9x1.6mm, Pitch 0.95mm, Lead Span 2.7mm, IPC Low Density)
pins: 1 VIN (power), 2 GND (power), 3 ~{SHDN} (in), 4 BYPASS, 5 VOUT (power)

## TC1014-2.85VCT713
designator U?
50 mA, 100 mA and 150 mA CMOS LDOs with Active-Low Shutdown and Reference Bypass, 5-Pin SOT-23, Extended Temperature, Tape and Reel
footprint SOT-23-CT5_N (SOT23, 5-Leads, Body 2.9x1.6mm, Pitch 0.95mm, Lead Span 2.7mm, IPC Medium Density)
footprint SOT-23-CT5_L (SOT23, 5-Leads, Body 2.9x1.6mm, Pitch 0.95mm, Lead Span 2.7mm, IPC High Density)
footprint SOT-23-CT5_M (SOT23, 5-Leads, Body 2.9x1.6mm, Pitch 0.95mm, Lead Span 2.7mm, IPC Low Density)
pins: 1 VIN (power), 2 GND (power), 3 ~{SHDN} (in), 4 BYPASS, 5 VOUT (power)

## TC1014-3.0VCT713
designator U?
50 mA, 100 mA and 150 mA CMOS LDOs with Active-Low Shutdown and Reference Bypass, 5-Pin SOT-23, Extended Temperature, Tape and Reel
footprint SOT-23-CT5_N (SOT23, 5-Leads, Body 2.9x1.6mm, Pitch 0.95mm, Lead Span 2.7mm, IPC Medium Density)
footprint SOT-23-CT5_L (SOT23, 5-Leads, Body 2.9x1.6mm, Pitch 0.95mm, Lead Span 2.7mm, IPC High Density)
footprint SOT-23-CT5_M (SOT23, 5-Leads, Body 2.9x1.6mm, Pitch 0.95mm, Lead Span 2.7mm, IPC Low Density)
pins: 1 VIN (power), 2 GND (power), 3 ~{SHDN} (in), 4 BYPASS, 5 VOUT (power)

## TC1014-3.3VCT713
designator U?
50 mA, 100 mA and 150 mA CMOS LDOs with Active-Low Shutdown and Reference Bypass, 5-Pin SOT-23, Extended Temperature, Tape and Reel
footprint SOT-23-CT5_N (SOT23, 5-Leads, Body 2.9x1.6mm, Pitch 0.95mm, Lead Span 2.7mm, IPC Medium Density)
footprint SOT-23-CT5_L (SOT23, 5-Leads, Body 2.9x1.6mm, Pitch 0.95mm, Lead Span 2.7mm, IPC High Density)
footprint SOT-23-CT5_M (SOT23, 5-Leads, Body 2.9x1.6mm, Pitch 0.95mm, Lead Span 2.7mm, IPC Low Density)
pins: 1 VIN (power), 2 GND (power), 3 ~{SHDN} (in), 4 BYPASS, 5 VOUT (power)

## TC1014-3.6VCT713
designator U?
50 mA, 100 mA and 150 mA CMOS LDOs with Active-Low Shutdown and Reference Bypass, 5-Pin SOT-23, Extended Temperature, Tape and Reel
footprint SOT-23-CT5_N (SOT23, 5-Leads, Body 2.9x1.6mm, Pitch 0.95mm, Lead Span 2.7mm, IPC Medium Density)
footprint SOT-23-CT5_L (SOT23, 5-Leads, Body 2.9x1.6mm, Pitch 0.95mm, Lead Span 2.7mm, IPC High Density)
footprint SOT-23-CT5_M (SOT23, 5-Leads, Body 2.9x1.6mm, Pitch 0.95mm, Lead Span 2.7mm, IPC Low Density)
pins: 1 VIN (power), 2 GND (power), 3 ~{SHDN} (in), 4 BYPASS, 5 VOUT (power)

## TC1014-4.0VCT713
designator U?
50 mA, 100 mA and 150 mA CMOS LDOs with Active-Low Shutdown and Reference Bypass, 5-Pin SOT-23, Extended Temperature, Tape and Reel
footprint SOT-23-CT5_N (SOT23, 5-Leads, Body 2.9x1.6mm, Pitch 0.95mm, Lead Span 2.7mm, IPC Medium Density)
footprint SOT-23-CT5_L (SOT23, 5-Leads, Body 2.9x1.6mm, Pitch 0.95mm, Lead Span 2.7mm, IPC High Density)
footprint SOT-23-CT5_M (SOT23, 5-Leads, Body 2.9x1.6mm, Pitch 0.95mm, Lead Span 2.7mm, IPC Low Density)
pins: 1 VIN (power), 2 GND (power), 3 ~{SHDN} (in), 4 BYPASS, 5 VOUT (power)

## TC1014-5.0VCT713
designator U?
50 mA, 100 mA and 150 mA CMOS LDOs with Active-Low Shutdown and Reference Bypass, 5-Pin SOT-23, Extended Temperature, Tape and Reel
footprint SOT-23-CT5_N (SOT23, 5-Leads, Body 2.9x1.6mm, Pitch 0.95mm, Lead Span 2.7mm, IPC Medium Density)
footprint SOT-23-CT5_L (SOT23, 5-Leads, Body 2.9x1.6mm, Pitch 0.95mm, Lead Span 2.7mm, IPC High Density)
footprint SOT-23-CT5_M (SOT23, 5-Leads, Body 2.9x1.6mm, Pitch 0.95mm, Lead Span 2.7mm, IPC Low Density)
pins: 1 VIN (power), 2 GND (power), 3 ~{SHDN} (in), 4 BYPASS, 5 VOUT (power)

## TC1015-1.8VCT713
designator U?
50 mA, 100 mA and 150 mA CMOS LDOs with Active-Low Shutdown and Reference Bypass, 5-Pin SOT-23, Extended Temperature, Tape and Reel
footprint SOT-23-CT5_N (SOT23, 5-Leads, Body 2.9x1.6mm, Pitch 0.95mm, Lead Span 2.7mm, IPC Medium Density)
footprint SOT-23-CT5_L (SOT23, 5-Leads, Body 2.9x1.6mm, Pitch 0.95mm, Lead Span 2.7mm, IPC High Density)
footprint SOT-23-CT5_M (SOT23, 5-Leads, Body 2.9x1.6mm, Pitch 0.95mm, Lead Span 2.7mm, IPC Low Density)
pins: 1 VIN (power), 2 GND (power), 3 ~{SHDN} (in), 4 BYPASS, 5 VOUT (power)

## TC1015-2.0VCT713
designator U?
50 mA, 100 mA and 150 mA CMOS LDOs with Active-Low Shutdown and Reference Bypass, 5-Pin SOT-23, Extended Temperature, Tape and Reel
footprint SOT-23-CT5_N (SOT23, 5-Leads, Body 2.9x1.6mm, Pitch 0.95mm, Lead Span 2.7mm, IPC Medium Density)
footprint SOT-23-CT5_L (SOT23, 5-Leads, Body 2.9x1.6mm, Pitch 0.95mm, Lead Span 2.7mm, IPC High Density)
footprint SOT-23-CT5_M (SOT23, 5-Leads, Body 2.9x1.6mm, Pitch 0.95mm, Lead Span 2.7mm, IPC Low Density)
pins: 1 VIN (power), 2 GND (power), 3 ~{SHDN} (in), 4 BYPASS, 5 VOUT (power)

## TC1015-2.5VCT713
designator U?
50 mA, 100 mA and 150 mA CMOS LDOs with Active-Low Shutdown and Reference Bypass, 5-Pin SOT-23, Extended Temperature, Tape and Reel
footprint SOT-23-CT5_N (SOT23, 5-Leads, Body 2.9x1.6mm, Pitch 0.95mm, Lead Span 2.7mm, IPC Medium Density)
footprint SOT-23-CT5_L (SOT23, 5-Leads, Body 2.9x1.6mm, Pitch 0.95mm, Lead Span 2.7mm, IPC High Density)
footprint SOT-23-CT5_M (SOT23, 5-Leads, Body 2.9x1.6mm, Pitch 0.95mm, Lead Span 2.7mm, IPC Low Density)
pins: 1 VIN (power), 2 GND (power), 3 ~{SHDN} (in), 4 BYPASS, 5 VOUT (power)

## TC1015-2.6VCT713
designator U?
50 mA, 100 mA and 150 mA CMOS LDOs with Active-Low Shutdown and Reference Bypass, 5-Pin SOT-23, Extended Temperature, Tape and Reel
footprint SOT-23-CT5_N (SOT23, 5-Leads, Body 2.9x1.6mm, Pitch 0.95mm, Lead Span 2.7mm, IPC Medium Density)
footprint SOT-23-CT5_L (SOT23, 5-Leads, Body 2.9x1.6mm, Pitch 0.95mm, Lead Span 2.7mm, IPC High Density)
footprint SOT-23-CT5_M (SOT23, 5-Leads, Body 2.9x1.6mm, Pitch 0.95mm, Lead Span 2.7mm, IPC Low Density)
pins: 1 VIN (power), 2 GND (power), 3 ~{SHDN} (in), 4 BYPASS, 5 VOUT (power)

## TC1015-2.7VCT713
designator U?
50 mA, 100 mA and 150 mA CMOS LDOs with Active-Low Shutdown and Reference Bypass, 5-Pin SOT-23, Extended Temperature, Tape and Reel
footprint SOT-23-CT5_N (SOT23, 5-Leads, Body 2.9x1.6mm, Pitch 0.95mm, Lead Span 2.7mm, IPC Medium Density)
footprint SOT-23-CT5_L (SOT23, 5-Leads, Body 2.9x1.6mm, Pitch 0.95mm, Lead Span 2.7mm, IPC High Density)
footprint SOT-23-CT5_M (SOT23, 5-Leads, Body 2.9x1.6mm, Pitch 0.95mm, Lead Span 2.7mm, IPC Low Density)
pins: 1 VIN (power), 2 GND (power), 3 ~{SHDN} (in), 4 BYPASS, 5 VOUT (power)

## TC1015-2.8VCT713
designator U?
50 mA, 100 mA and 150 mA CMOS LDOs with Active-Low Shutdown and Reference Bypass, 5-Pin SOT-23, Extended Temperature, Tape and Reel
footprint SOT-23-CT5_N (SOT23, 5-Leads, Body 2.9x1.6mm, Pitch 0.95mm, Lead Span 2.7mm, IPC Medium Density)
footprint SOT-23-CT5_L (SOT23, 5-Leads, Body 2.9x1.6mm, Pitch 0.95mm, Lead Span 2.7mm, IPC High Density)
footprint SOT-23-CT5_M (SOT23, 5-Leads, Body 2.9x1.6mm, Pitch 0.95mm, Lead Span 2.7mm, IPC Low Density)
pins: 1 VIN (power), 2 GND (power), 3 ~{SHDN} (in), 4 BYPASS, 5 VOUT (power)

## TC1015-2.85VCT713
designator U?
50 mA, 100 mA and 150 mA CMOS LDOs with Active-Low Shutdown and Reference Bypass, 5-Pin SOT-23, Extended Temperature, Tape and Reel
footprint SOT-23-CT5_N (SOT23, 5-Leads, Body 2.9x1.6mm, Pitch 0.95mm, Lead Span 2.7mm, IPC Medium Density)
footprint SOT-23-CT5_L (SOT23, 5-Leads, Body 2.9x1.6mm, Pitch 0.95mm, Lead Span 2.7mm, IPC High Density)
footprint SOT-23-CT5_M (SOT23, 5-Leads, Body 2.9x1.6mm, Pitch 0.95mm, Lead Span 2.7mm, IPC Low Density)
pins: 1 VIN (power), 2 GND (power), 3 ~{SHDN} (in), 4 BYPASS, 5 VOUT (power)

## TC1015-3.0VCT713
designator U?
50 mA, 100 mA and 150 mA CMOS LDOs with Active-Low Shutdown and Reference Bypass, 5-Pin SOT-23, Extended Temperature, Tape and Reel
footprint SOT-23-CT5_N (SOT23, 5-Leads, Body 2.9x1.6mm, Pitch 0.95mm, Lead Span 2.7mm, IPC Medium Density)
footprint SOT-23-CT5_L (SOT23, 5-Leads, Body 2.9x1.6mm, Pitch 0.95mm, Lead Span 2.7mm, IPC High Density)
footprint SOT-23-CT5_M (SOT23, 5-Leads, Body 2.9x1.6mm, Pitch 0.95mm, Lead Span 2.7mm, IPC Low Density)
pins: 1 VIN (power), 2 GND (power), 3 ~{SHDN} (in), 4 BYPASS, 5 VOUT (power)

## TC1015-3.1VCT713
designator U?
50 mA, 100 mA and 150 mA CMOS LDOs with Active-Low Shutdown and Reference Bypass, 5-Pin SOT-23, Extended Temperature, Tape and Reel
footprint SOT-23-CT5_N (SOT23, 5-Leads, Body 2.9x1.6mm, Pitch 0.95mm, Lead Span 2.7mm, IPC Medium Density)
footprint SOT-23-CT5_L (SOT23, 5-Leads, Body 2.9x1.6mm, Pitch 0.95mm, Lead Span 2.7mm, IPC High Density)
footprint SOT-23-CT5_M (SOT23, 5-Leads, Body 2.9x1.6mm, Pitch 0.95mm, Lead Span 2.7mm, IPC Low Density)
pins: 1 VIN (power), 2 GND (power), 3 ~{SHDN} (in), 4 BYPASS, 5 VOUT (power)

## TC1015-3.2VCT713
designator U?
50 mA, 100 mA and 150 mA CMOS LDOs with Active-Low Shutdown and Reference Bypass, 5-Pin SOT-23, Extended Temperature, Tape and Reel
footprint SOT-23-CT5_N (SOT23, 5-Leads, Body 2.9x1.6mm, Pitch 0.95mm, Lead Span 2.7mm, IPC Medium Density)
footprint SOT-23-CT5_L (SOT23, 5-Leads, Body 2.9x1.6mm, Pitch 0.95mm, Lead Span 2.7mm, IPC High Density)
footprint SOT-23-CT5_M (SOT23, 5-Leads, Body 2.9x1.6mm, Pitch 0.95mm, Lead Span 2.7mm, IPC Low Density)
pins: 1 VIN (power), 2 GND (power), 3 ~{SHDN} (in), 4 BYPASS, 5 VOUT (power)

## TC1015-3.3VCT713
designator U?
50 mA, 100 mA and 150 mA CMOS LDOs with Active-Low Shutdown and Reference Bypass, 5-Pin SOT-23, Extended Temperature, Tape and Reel
footprint SOT-23-CT5_N (SOT23, 5-Leads, Body 2.9x1.6mm, Pitch 0.95mm, Lead Span 2.7mm, IPC Medium Density)
footprint SOT-23-CT5_L (SOT23, 5-Leads, Body 2.9x1.6mm, Pitch 0.95mm, Lead Span 2.7mm, IPC High Density)
footprint SOT-23-CT5_M (SOT23, 5-Leads, Body 2.9x1.6mm, Pitch 0.95mm, Lead Span 2.7mm, IPC Low Density)
pins: 1 VIN (power), 2 GND (power), 3 ~{SHDN} (in), 4 BYPASS, 5 VOUT (power)

## TC1015-3.6VCT713
designator U?
50 mA, 100 mA and 150 mA CMOS LDOs with Active-Low Shutdown and Reference Bypass, 5-Pin SOT-23, Extended Temperature, Tape and Reel
footprint SOT-23-CT5_N (SOT23, 5-Leads, Body 2.9x1.6mm, Pitch 0.95mm, Lead Span 2.7mm, IPC Medium Density)
footprint SOT-23-CT5_L (SOT23, 5-Leads, Body 2.9x1.6mm, Pitch 0.95mm, Lead Span 2.7mm, IPC High Density)
footprint SOT-23-CT5_M (SOT23, 5-Leads, Body 2.9x1.6mm, Pitch 0.95mm, Lead Span 2.7mm, IPC Low Density)
pins: 1 VIN (power), 2 GND (power), 3 ~{SHDN} (in), 4 BYPASS, 5 VOUT (power)

## TC1015-3.8VCT713
designator U?
50 mA, 100 mA and 150 mA CMOS LDOs with Active-Low Shutdown and Reference Bypass, 5-Pin SOT-23, Extended Temperature, Tape and Reel
footprint SOT-23-CT5_N (SOT23, 5-Leads, Body 2.9x1.6mm, Pitch 0.95mm, Lead Span 2.7mm, IPC Medium Density)
footprint SOT-23-CT5_L (SOT23, 5-Leads, Body 2.9x1.6mm, Pitch 0.95mm, Lead Span 2.7mm, IPC High Density)
footprint SOT-23-CT5_M (SOT23, 5-Leads, Body 2.9x1.6mm, Pitch 0.95mm, Lead Span 2.7mm, IPC Low Density)
pins: 1 VIN (power), 2 GND (power), 3 ~{SHDN} (in), 4 BYPASS, 5 VOUT (power)

## TC1015-4.0VCT713
designator U?
50 mA, 100 mA and 150 mA CMOS LDOs with Active-Low Shutdown and Reference Bypass, 5-Pin SOT-23, Extended Temperature, Tape and Reel
footprint SOT-23-CT5_N (SOT23, 5-Leads, Body 2.9x1.6mm, Pitch 0.95mm, Lead Span 2.7mm, IPC Medium Density)
footprint SOT-23-CT5_L (SOT23, 5-Leads, Body 2.9x1.6mm, Pitch 0.95mm, Lead Span 2.7mm, IPC High Density)
footprint SOT-23-CT5_M (SOT23, 5-Leads, Body 2.9x1.6mm, Pitch 0.95mm, Lead Span 2.7mm, IPC Low Density)
pins: 1 VIN (power), 2 GND (power), 3 ~{SHDN} (in), 4 BYPASS, 5 VOUT (power)

## TC1015-5.0VCT713
designator U?
50 mA, 100 mA and 150 mA CMOS LDOs with Active-Low Shutdown and Reference Bypass, 5-Pin SOT-23, Extended Temperature, Tape and Reel
footprint SOT-23-CT5_N (SOT23, 5-Leads, Body 2.9x1.6mm, Pitch 0.95mm, Lead Span 2.7mm, IPC Medium Density)
footprint SOT-23-CT5_L (SOT23, 5-Leads, Body 2.9x1.6mm, Pitch 0.95mm, Lead Span 2.7mm, IPC High Density)
footprint SOT-23-CT5_M (SOT23, 5-Leads, Body 2.9x1.6mm, Pitch 0.95mm, Lead Span 2.7mm, IPC Low Density)
pins: 1 VIN (power), 2 GND (power), 3 ~{SHDN} (in), 4 BYPASS, 5 VOUT (power)

## TC1016-1.8VCTTR
designator U?
800 mA Fixed Low Dropout Positive Regulator, 5-Pin SOT-23, Extended Temperature, Tape and Reel
footprint SOT-23-CT5_N (SOT23, 5-Leads, Body 2.9x1.6mm, Pitch 0.95mm, Lead Span 2.7mm, IPC Medium Density)
footprint SOT-23-CT5_L (SOT23, 5-Leads, Body 2.9x1.6mm, Pitch 0.95mm, Lead Span 2.7mm, IPC High Density)
footprint SOT-23-CT5_M (SOT23, 5-Leads, Body 2.9x1.6mm, Pitch 0.95mm, Lead Span 2.7mm, IPC Low Density)
pins: 1 VIN (power), 2 GND (power), 3 ~{SHDN} (in), 4 NC, 5 VOUT (power)

## TC1016-1.8VLTTR
designator U?
800 mA Fixed Low Dropout Positive Regulator, 5-Pin SC-70, Extended Temperature, Tape and Reel
footprint SC70-LT5_N (SOT353, 5-Leads, Body 2x1.3mm, Pitch 0.65mm, Lead Span 2.1mm, IPC Medium Density)
footprint SC70-LT5_L (SOT353, 5-Leads, Body 2x1.3mm, Pitch 0.65mm, Lead Span 2.1mm, IPC High Density)
footprint SC70-LT5_M (SOT353, 5-Leads, Body 2x1.3mm, Pitch 0.65mm, Lead Span 2.1mm, IPC Low Density)
pins: 1 ~{SHDN} (in), 2 NC, 3 GND (power), 4 VOUT (power), 5 VIN (power)

## TC1016-2.7VLTTR
designator U?
800 mA Fixed Low Dropout Positive Regulator, 5-Pin SC-70, Extended Temperature, Tape and Reel
footprint SC70-LT5_N (SOT353, 5-Leads, Body 2x1.3mm, Pitch 0.65mm, Lead Span 2.1mm, IPC Medium Density)
footprint SC70-LT5_L (SOT353, 5-Leads, Body 2x1.3mm, Pitch 0.65mm, Lead Span 2.1mm, IPC High Density)
footprint SC70-LT5_M (SOT353, 5-Leads, Body 2x1.3mm, Pitch 0.65mm, Lead Span 2.1mm, IPC Low Density)
pins: 1 ~{SHDN} (in), 2 NC, 3 GND (power), 4 VOUT (power), 5 VIN (power)

## TC1016-2.8VLTTR
designator U?
800 mA Fixed Low Dropout Positive Regulator, 5-Pin SC-70, Extended Temperature, Tape and Reel
footprint SC70-LT5_N (SOT353, 5-Leads, Body 2x1.3mm, Pitch 0.65mm, Lead Span 2.1mm, IPC Medium Density)
footprint SC70-LT5_L (SOT353, 5-Leads, Body 2x1.3mm, Pitch 0.65mm, Lead Span 2.1mm, IPC High Density)
footprint SC70-LT5_M (SOT353, 5-Leads, Body 2x1.3mm, Pitch 0.65mm, Lead Span 2.1mm, IPC Low Density)
pins: 1 ~{SHDN} (in), 2 NC, 3 GND (power), 4 VOUT (power), 5 VIN (power)

## TC1016-2.85VLTTR
designator U?
800 mA Fixed Low Dropout Positive Regulator, 5-Pin SC-70, Extended Temperature, Tape and Reel
footprint SC70-LT5_N (SOT353, 5-Leads, Body 2x1.3mm, Pitch 0.65mm, Lead Span 2.1mm, IPC Medium Density)
footprint SC70-LT5_L (SOT353, 5-Leads, Body 2x1.3mm, Pitch 0.65mm, Lead Span 2.1mm, IPC High Density)
footprint SC70-LT5_M (SOT353, 5-Leads, Body 2x1.3mm, Pitch 0.65mm, Lead Span 2.1mm, IPC Low Density)
pins: 1 ~{SHDN} (in), 2 NC, 3 GND (power), 4 VOUT (power), 5 VIN (power)

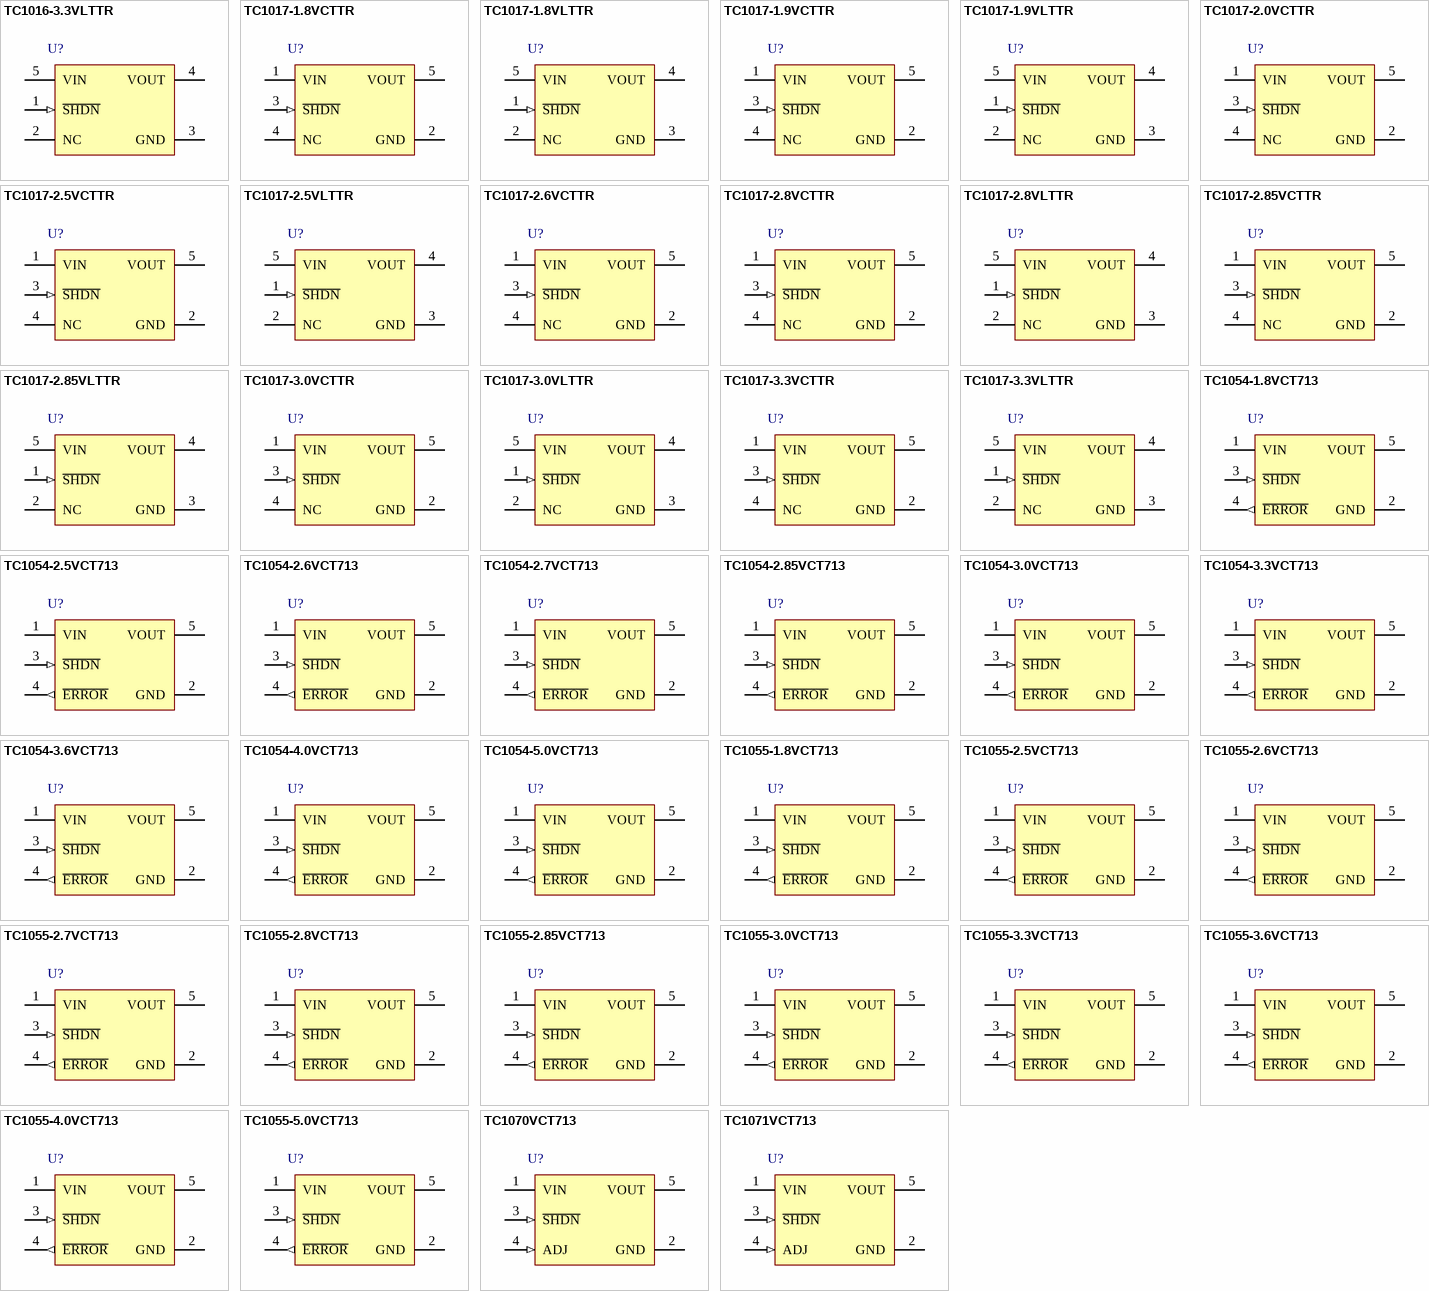
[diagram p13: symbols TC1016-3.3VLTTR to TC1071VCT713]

## TC1016-3.3VLTTR
designator U?
800 mA Fixed Low Dropout Positive Regulator, 5-Pin SC-70, Extended Temperature, Tape and Reel
footprint SC70-LT5_N (SOT353, 5-Leads, Body 2x1.3mm, Pitch 0.65mm, Lead Span 2.1mm, IPC Medium Density)
footprint SC70-LT5_L (SOT353, 5-Leads, Body 2x1.3mm, Pitch 0.65mm, Lead Span 2.1mm, IPC High Density)
footprint SC70-LT5_M (SOT353, 5-Leads, Body 2x1.3mm, Pitch 0.65mm, Lead Span 2.1mm, IPC Low Density)
pins: 1 ~{SHDN} (in), 2 NC, 3 GND (power), 4 VOUT (power), 5 VIN (power)

## TC1017-1.8VCTTR
designator U?
150 mA, Tiny CMOS LDO with Shutdown, 5-Pin SOT-23, Extended Temperature, Tape and Reel
footprint SOT-23-CT5_N (SOT23, 5-Leads, Body 2.9x1.6mm, Pitch 0.95mm, Lead Span 2.7mm, IPC Medium Density)
footprint SOT-23-CT5_L (SOT23, 5-Leads, Body 2.9x1.6mm, Pitch 0.95mm, Lead Span 2.7mm, IPC High Density)
footprint SOT-23-CT5_M (SOT23, 5-Leads, Body 2.9x1.6mm, Pitch 0.95mm, Lead Span 2.7mm, IPC Low Density)
pins: 1 VIN (power), 2 GND (power), 3 ~{SHDN} (in), 4 NC, 5 VOUT (power)

## TC1017-1.8VLTTR
designator U?
150 mA, Tiny CMOS LDO with Shutdown, 5-Pin SC-70, Extended Temperature, Tape and Reel
footprint SC70-LT5_N (SOT353, 5-Leads, Body 2x1.3mm, Pitch 0.65mm, Lead Span 2.1mm, IPC Medium Density)
footprint SC70-LT5_L (SOT353, 5-Leads, Body 2x1.3mm, Pitch 0.65mm, Lead Span 2.1mm, IPC High Density)
footprint SC70-LT5_M (SOT353, 5-Leads, Body 2x1.3mm, Pitch 0.65mm, Lead Span 2.1mm, IPC Low Density)
pins: 1 ~{SHDN} (in), 2 NC, 3 GND (power), 4 VOUT (power), 5 VIN (power)

## TC1017-1.9VCTTR
designator U?
150 mA, Tiny CMOS LDO with Shutdown, 5-Pin SOT-23, Extended Temperature, Tape and Reel
footprint SOT-23-CT5_N (SOT23, 5-Leads, Body 2.9x1.6mm, Pitch 0.95mm, Lead Span 2.7mm, IPC Medium Density)
footprint SOT-23-CT5_L (SOT23, 5-Leads, Body 2.9x1.6mm, Pitch 0.95mm, Lead Span 2.7mm, IPC High Density)
footprint SOT-23-CT5_M (SOT23, 5-Leads, Body 2.9x1.6mm, Pitch 0.95mm, Lead Span 2.7mm, IPC Low Density)
pins: 1 VIN (power), 2 GND (power), 3 ~{SHDN} (in), 4 NC, 5 VOUT (power)

## TC1017-1.9VLTTR
designator U?
150 mA, Tiny CMOS LDO with Shutdown, 5-Pin SC-70, Extended Temperature, Tape and Reel
footprint SC70-LT5_N (SOT353, 5-Leads, Body 2x1.3mm, Pitch 0.65mm, Lead Span 2.1mm, IPC Medium Density)
footprint SC70-LT5_L (SOT353, 5-Leads, Body 2x1.3mm, Pitch 0.65mm, Lead Span 2.1mm, IPC High Density)
footprint SC70-LT5_M (SOT353, 5-Leads, Body 2x1.3mm, Pitch 0.65mm, Lead Span 2.1mm, IPC Low Density)
pins: 1 ~{SHDN} (in), 2 NC, 3 GND (power), 4 VOUT (power), 5 VIN (power)

## TC1017-2.0VCTTR
designator U?
150 mA, Tiny CMOS LDO with Shutdown, 5-Pin SOT-23, Extended Temperature, Tape and Reel
footprint SOT-23-CT5_N (SOT23, 5-Leads, Body 2.9x1.6mm, Pitch 0.95mm, Lead Span 2.7mm, IPC Medium Density)
footprint SOT-23-CT5_L (SOT23, 5-Leads, Body 2.9x1.6mm, Pitch 0.95mm, Lead Span 2.7mm, IPC High Density)
footprint SOT-23-CT5_M (SOT23, 5-Leads, Body 2.9x1.6mm, Pitch 0.95mm, Lead Span 2.7mm, IPC Low Density)
pins: 1 VIN (power), 2 GND (power), 3 ~{SHDN} (in), 4 NC, 5 VOUT (power)

## TC1017-2.5VCTTR
designator U?
150 mA, Tiny CMOS LDO with Shutdown, 5-Pin SOT-23, Extended Temperature, Tape and Reel
footprint SOT-23-CT5_N (SOT23, 5-Leads, Body 2.9x1.6mm, Pitch 0.95mm, Lead Span 2.7mm, IPC Medium Density)
footprint SOT-23-CT5_L (SOT23, 5-Leads, Body 2.9x1.6mm, Pitch 0.95mm, Lead Span 2.7mm, IPC High Density)
footprint SOT-23-CT5_M (SOT23, 5-Leads, Body 2.9x1.6mm, Pitch 0.95mm, Lead Span 2.7mm, IPC Low Density)
pins: 1 VIN (power), 2 GND (power), 3 ~{SHDN} (in), 4 NC, 5 VOUT (power)

## TC1017-2.5VLTTR
designator U?
150 mA, Tiny CMOS LDO with Shutdown, 5-Pin SC-70, Extended Temperature, Tape and Reel
footprint SC70-LT5_N (SOT353, 5-Leads, Body 2x1.3mm, Pitch 0.65mm, Lead Span 2.1mm, IPC Medium Density)
footprint SC70-LT5_L (SOT353, 5-Leads, Body 2x1.3mm, Pitch 0.65mm, Lead Span 2.1mm, IPC High Density)
footprint SC70-LT5_M (SOT353, 5-Leads, Body 2x1.3mm, Pitch 0.65mm, Lead Span 2.1mm, IPC Low Density)
pins: 1 ~{SHDN} (in), 2 NC, 3 GND (power), 4 VOUT (power), 5 VIN (power)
